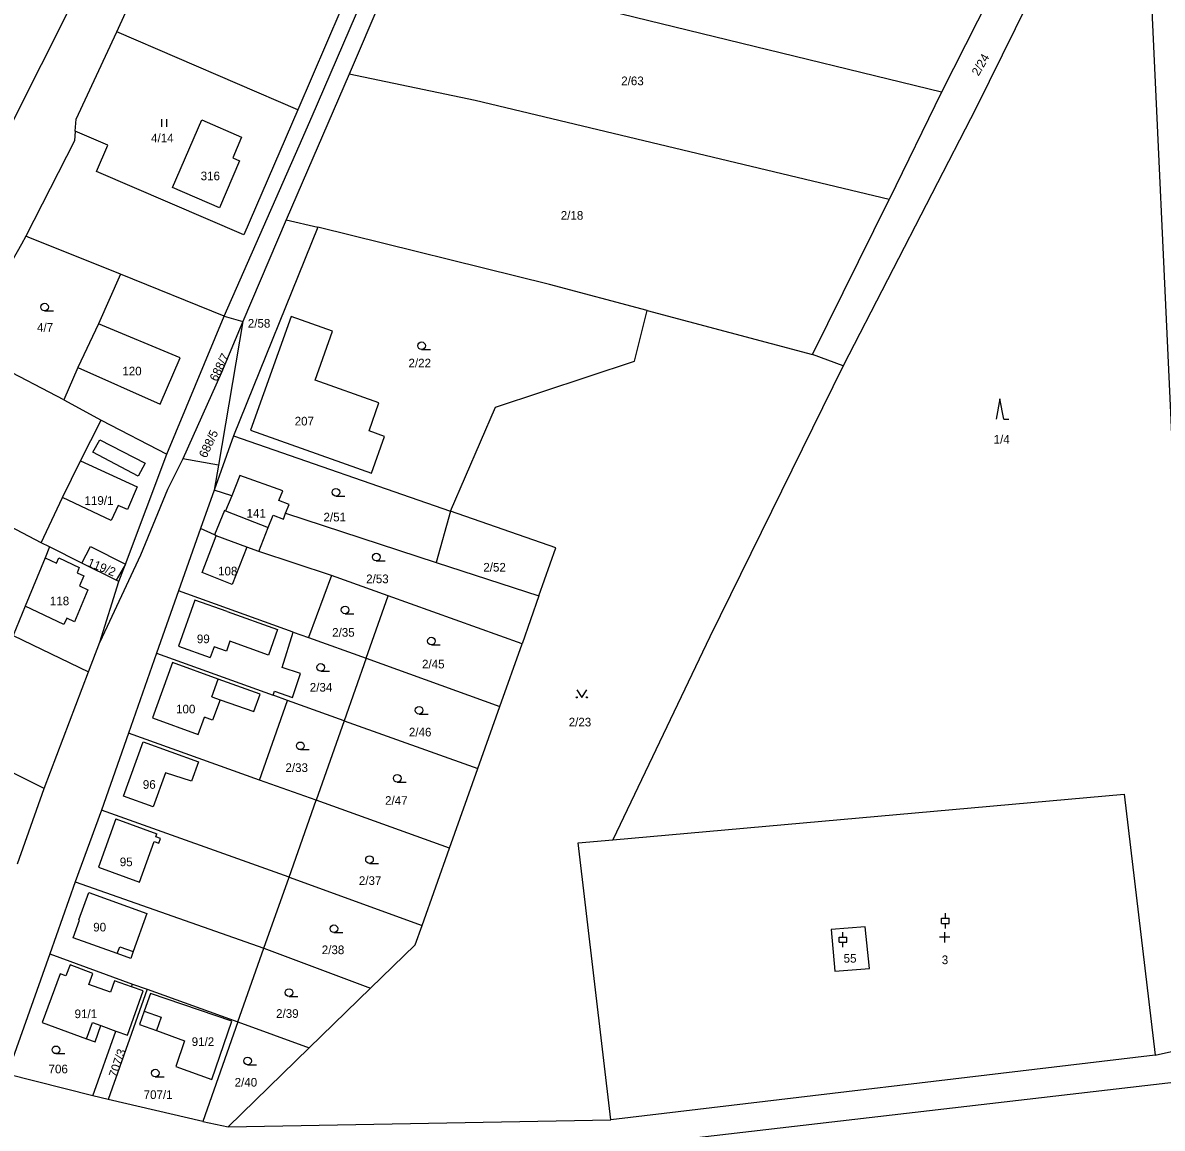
# Model space of a CAD drawing. Extents: x -747333 to -743907, y -1134120 to -1130051.
# Drawn here: x -746109.8 to -745885.9, y -1131640.4 to -1131423.1 of the extents above; entities that cross this region are included whole.
import ezdxf

# ---------------------------------------------------------------- set-up
doc = ezdxf.new("R2010")
doc.units = 0
for name, color, linetype in [('Hranice parcel', 7, 'Continuous'), ('Parcelní čísla', 7, 'Continuous'), ('Vnitřní kresba', 7, 'Continuous'), ('Značky kultur', 7, 'Continuous')]:
    doc.layers.add(name, color=color, linetype=linetype)

msp = doc.modelspace()

# ---------------------------------------------------------------- linework, layer by layer
at = {"layer": 'Hranice parcel'}
for p, q in [((-746091.29, -1131424.93), (-746079.61, -1131398.84)), ((-746036.2, -1131411.06), (-746045.64, -1131433.21)), ((-745919.41, -1131417.32), (-745929.22, -1131436.79)), ((-746055.78, -1131440.25), (-746091.29, -1131424.93)), ((-746045.64, -1131433.21), (-746058.01, -1131461.89)), ((-745929.22, -1131436.79), (-745939.56, -1131457.86)), ((-746099.49, -1131444.41), (-746099.65, -1131446.33)), ((-746099.65, -1131446.33), (-746109.2, -1131465.08)), ((-746070.2, -1131480.79), (-746055.46, -1131447.33)), ((-745954.58, -1131488.31), (-745939.56, -1131457.86)), ((-746051.84, -1131463.28), (-746068.39, -1131504.28)), ((-746058.01, -1131461.89), (-746066.53, -1131481.86)), ((-746058.01, -1131461.89), (-746051.84, -1131463.28)), ((-746070.2, -1131480.79), (-746090.62, -1131472.56)), ((-746081.52, -1131507.94), (-746070.2, -1131480.79)), ((-746070.2, -1131480.79), (-746066.53, -1131481.86)), ((-745987.12, -1131479.66), (-745954.58, -1131488.31)), ((-746066.53, -1131481.86), (-746071.31, -1131510.04)), ((-746101.76, -1131497.26), (-746121.6, -1131486.86)), ((-745948.59, -1131490.54), (-745954.58, -1131488.31)), ((-746101.76, -1131497.26), (-746094.4, -1131501.22)), ((-746094.4, -1131501.22), (-746081.52, -1131507.94)), ((-746068.39, -1131504.28), (-746072.17, -1131514.96)), ((-746068.39, -1131504.28), (-746025.75, -1131519.12)), ((-746089.64, -1131529.49), (-746081.52, -1131507.94)), ((-746071.31, -1131510.04), (-746078.33, -1131508.83)), ((-746071.31, -1131510.04), (-746072.17, -1131514.96)), ((-746106.2, -1131525.3), (-746133.59, -1131510.98)), ((-746072.17, -1131514.96), (-746074.85, -1131522.52)), ((-746058.14, -1131519.53), (-746028.56, -1131529.17)), ((-746025.75, -1131519.12), (-746028.56, -1131529.17)), ((-746074.85, -1131522.52), (-746079.17, -1131534.78)), ((-746104.53, -1131526.13), (-746106.2, -1131525.3)), ((-746098.18, -1131529.3), (-746104.53, -1131526.13)), ((-746049.11, -1131531.76), (-746063.44, -1131527.04)), ((-746090.93, -1131532.92), (-746089.64, -1131529.49)), ((-746028.56, -1131529.17), (-746008.35, -1131535.75)), ((-746094.68, -1131544.83), (-746090.93, -1131532.92)), ((-746049.11, -1131531.76), (-746053.64, -1131543.96)), ((-746038, -1131535.74), (-746049.11, -1131531.76)), ((-746079.17, -1131534.78), (-746083.5, -1131547.04)), ((-746056.65, -1131542.87), (-746079.17, -1131534.78)), ((-746042.33, -1131548.02), (-746038, -1131535.74)), ((-746011.68, -1131545.17), (-746038, -1131535.74)), ((-746008.35, -1131535.75), (-746011.68, -1131545.17)), ((-746111.71, -1131543.57), (-746096.91, -1131550.67)), ((-746056.65, -1131542.87), (-746053.64, -1131543.96)), ((-746053.64, -1131543.96), (-746042.33, -1131548.02)), ((-746096.91, -1131550.67), (-746094.68, -1131544.83)), ((-746016.06, -1131557.46), (-746011.68, -1131545.17)), ((-746083.5, -1131547.04), (-746089.04, -1131562.74)), ((-746083.5, -1131547.04), (-746060.6, -1131555.29)), ((-746042.33, -1131548.02), (-746046.66, -1131560.32)), ((-746042.33, -1131548.02), (-746016.06, -1131557.46)), ((-746105.62, -1131573.59), (-746096.91, -1131550.67)), ((-746057.78, -1131556.31), (-746060.6, -1131555.29)), ((-746063.27, -1131571.95), (-746057.78, -1131556.31)), ((-746046.66, -1131560.32), (-746057.78, -1131556.31)), ((-746020.37, -1131569.7), (-746016.06, -1131557.46)), ((-746046.66, -1131560.32), (-746052.16, -1131575.92)), ((-746046.66, -1131560.32), (-746020.37, -1131569.7)), ((-746089.04, -1131562.74), (-746094.36, -1131577.83)), ((-746063.27, -1131571.95), (-746089.04, -1131562.74)), ((-746025.95, -1131585.34), (-746020.37, -1131569.7)), ((-746052.16, -1131575.92), (-746063.27, -1131571.95)), ((-746110.85, -1131588.4), (-746105.62, -1131573.59)), ((-745993.84, -1131583.67), (-745893.35, -1131574.74)), ((-745893.35, -1131574.74), (-745887.25, -1131625.98)), ((-746057.47, -1131591.02), (-746052.16, -1131575.92)), ((-746025.95, -1131585.34), (-746052.16, -1131575.92)), ((-746094.36, -1131577.83), (-746099.48, -1131591.93)), ((-746057.47, -1131591.02), (-746094.36, -1131577.83)), ((-746031.34, -1131600.5), (-746025.95, -1131585.34)), ((-746062.41, -1131605), (-746057.47, -1131591.02)), ((-746057.47, -1131591.02), (-746031.34, -1131600.5)), ((-746099.48, -1131591.93), (-746104.52, -1131606.12)), ((-746099.48, -1131591.93), (-746062.41, -1131605)), ((-746104.52, -1131606.12), (-746112.88, -1131629.7)), ((-746104.52, -1131606.12), (-746088.22, -1131612.03)), ((-746067.51, -1131619.48), (-746062.41, -1131605)), ((-746062.41, -1131605), (-746041.46, -1131612.82)), ((-746085.34, -1131613.06), (-746093.05, -1131634.69)), ((-746088.41, -1131612.57), (-746088.22, -1131612.03)), ((-746088.22, -1131612.03), (-746085.34, -1131613.06)), ((-746085.34, -1131613.06), (-746067.51, -1131619.48)), ((-746041.46, -1131612.82), (-746053.5, -1131624.53)), ((-746067.51, -1131619.48), (-746074.4, -1131639.02)), ((-746067.51, -1131619.48), (-746053.5, -1131624.53)), ((-746096.04, -1131633.97), (-746091.51, -1131621.25)), ((-746053.5, -1131624.53), (-746069.45, -1131640.11)), ((-745887.25, -1131625.98), (-745877.87, -1131623.88)), ((-745887.25, -1131625.98), (-745994.2, -1131638.7)), ((-746096.04, -1131633.97), (-746112.88, -1131629.7)), ((-746093.05, -1131634.69), (-746096.04, -1131633.97)), ((-746074.4, -1131639.02), (-746093.05, -1131634.69)), ((-746074.4, -1131639.02), (-746069.45, -1131640.11)), ((-746069.45, -1131640.11), (-745994.2, -1131638.7))]:
    msp.add_line(p, q, dxfattribs=at)
for points in [[(-745889.16, -1131372.37), (-745922.43, -1131439.85), (-745948.59, -1131490.54)], [(-745877.87, -1131623.88), (-745879.16, -1131608.6), (-745883.81, -1131508.22), (-745888.44, -1131407.94), (-745889.16, -1131372.37)], [(-746090.75, -1131400.54), (-746121.73, -1131462.2), (-746150.71, -1131520.43), (-746173.33, -1131568.01)], [(-746079.61, -1131398.84), (-746044.46, -1131414), (-746055.78, -1131440.25)], [(-746055.46, -1131447.33), (-746052.93, -1131441.47), (-746038.19, -1131407.28)], [(-745929.22, -1131436.79), (-746018.47, -1131414.97), (-746036.2, -1131411.06)], [(-746099.49, -1131444.41), (-746099.29, -1131442.11), (-746091.29, -1131424.93)], [(-745939.56, -1131457.86), (-746020.87, -1131438.42), (-746045.64, -1131433.21)], [(-746055.78, -1131440.25), (-746066.38, -1131464.83), (-746095.3, -1131452.34), (-746093.06, -1131447.16), (-746099.49, -1131444.41)], [(-746074.64, -1131442.24), (-746066.8, -1131445.62), (-746068.54, -1131449.69), (-746067.19, -1131450.29), (-746071.16, -1131459.52), (-746080.38, -1131455.54), (-746074.64, -1131442.24)], [(-745987.12, -1131479.66), (-746006.29, -1131474.57), (-746051.84, -1131463.28)], [(-746109.2, -1131465.08), (-746110.05, -1131466.67), (-746121.6, -1131486.86)], [(-746090.62, -1131472.56), (-746108.75, -1131465.26), (-746109.2, -1131465.08)], [(-746090.62, -1131472.56), (-746094.92, -1131482.29), (-746098.99, -1131490.89), (-746101.76, -1131497.26)], [(-746052.32, -1131493.39), (-746048.95, -1131483.73), (-746057.08, -1131480.84), (-746065.02, -1131503.16), (-746041.26, -1131511.62), (-746038.7, -1131504.42), (-746041.76, -1131503.33), (-746039.8, -1131497.85), (-746052.32, -1131493.39)], [(-746025.75, -1131519.12), (-746016.9, -1131498.7), (-745989.55, -1131489.64), (-745987.12, -1131479.66)], [(-746066.53, -1131481.86), (-746070.75, -1131491.89), (-746078.33, -1131508.83)], [(-745948.59, -1131490.54), (-745974.76, -1131543.78), (-745993.84, -1131583.67)], [(-746106.2, -1131525.3), (-746102, -1131516.42), (-746098.43, -1131509.2), (-746094.4, -1131501.22)], [(-746078.33, -1131508.83), (-746081.34, -1131514.84), (-746086.66, -1131527.76), (-746094.68, -1131544.83)], [(-746067.15, -1131512.07), (-746068.75, -1131516.07), (-746072.17, -1131514.96)], [(-746058.14, -1131519.53), (-746057.45, -1131517.8), (-746059.47, -1131517), (-746058.72, -1131515.11), (-746067.15, -1131512.07)], [(-746060.61, -1131519.88), (-746058.59, -1131520.68), (-746058.14, -1131519.53)], [(-746008.35, -1131535.75), (-746005.02, -1131526.33), (-746025.75, -1131519.12)], [(-746063.44, -1131527.04), (-746061.57, -1131522.3), (-746060.61, -1131519.88)], [(-746063.44, -1131527.04), (-746065.8, -1131526.18), (-746071.78, -1131523.98), (-746072.11, -1131523.76), (-746074.85, -1131522.52)], [(-746104.53, -1131526.13), (-746105.42, -1131528.29), (-746109.33, -1131537.8), (-746111.71, -1131543.57)], [(-746098.18, -1131529.3), (-746096.51, -1131526.05), (-746089.64, -1131529.49)], [(-746090.93, -1131532.92), (-746091.45, -1131532.66), (-746098.18, -1131529.3)], [(-746060.6, -1131555.29), (-746060.34, -1131554.48), (-746056.82, -1131555.72), (-746055.25, -1131551), (-746058.86, -1131549.83), (-746056.65, -1131542.87)], [(-746105.62, -1131573.59), (-746112.3, -1131570.23), (-746119.76, -1131566.48)], [(-745994.2, -1131638.7), (-746000.67, -1131584.28), (-745993.84, -1131583.67)], [(-746041.46, -1131612.82), (-746032.7, -1131604.32), (-746031.34, -1131600.5)], [(-745950.23, -1131609.5), (-745943.41, -1131608.97), (-745944.27, -1131600.75), (-745950.91, -1131601.29), (-745950.23, -1131609.5)], [(-746088.41, -1131612.57), (-746091.78, -1131611.4), (-746092.55, -1131613.63), (-746096.85, -1131612.12), (-746096.04, -1131609.98), (-746100.51, -1131608.28), (-746101.32, -1131610.42)], [(-746101.32, -1131610.42), (-746102.46, -1131609.99), (-746105.97, -1131619.61)], [(-746091.51, -1131621.25), (-746089.21, -1131622.09), (-746086.16, -1131613.35), (-746088.41, -1131612.57)], [(-746079.75, -1131628.25), (-746072.63, -1131630.79), (-746068.71, -1131619.33), (-746084.68, -1131613.85), (-746085.92, -1131617.33), (-746086.87, -1131619.99), (-746083.54, -1131621.18), (-746078.01, -1131623.15), (-746079.75, -1131628.25)], [(-746105.97, -1131619.61), (-746097.26, -1131622.76), (-746095.6, -1131623.36), (-746094.44, -1131620.17), (-746091.51, -1131621.25)], [(-746011.54, -1131646.14), (-745993.09, -1131644.03), (-745877.4, -1131630.6)]]:
    msp.add_lwpolyline(points, dxfattribs=at)
at = {"layer": 'Vnitřní kresba'}
for p, q in [((-746078.88, -1131488.97), (-746094.92, -1131482.29)), ((-746082.79, -1131498.11), (-746078.88, -1131488.97)), ((-746098.99, -1131490.89), (-746082.79, -1131498.11)), ((-746098.43, -1131509.2), (-746087.32, -1131514.31)), ((-746087.32, -1131514.31), (-746089.24, -1131518.76)), ((-746092.41, -1131520.95), (-746102, -1131516.42)), ((-746068.75, -1131516.07), (-746069.95, -1131519.06)), ((-746091.06, -1131518), (-746092.41, -1131520.95)), ((-746089.24, -1131518.76), (-746091.06, -1131518)), ((-746070.19, -1131518.96), (-746072.11, -1131523.76)), ((-746069.95, -1131519.06), (-746070.19, -1131518.96)), ((-746069.95, -1131519.06), (-746061.57, -1131522.3)), ((-746074.58, -1131531.19), (-746071.78, -1131523.98)), ((-746065.8, -1131526.18), (-746068.67, -1131533.49)), ((-746105.42, -1131528.29), (-746103.17, -1131529.3)), ((-746103.17, -1131529.3), (-746102.7, -1131528.25)), ((-746102.7, -1131528.25), (-746098.72, -1131530.19)), ((-746098.72, -1131530.19), (-746099.14, -1131531.24)), ((-746089.64, -1131529.49), (-746091.45, -1131532.66)), ((-746099.14, -1131531.24), (-746097.83, -1131531.81)), ((-746097.83, -1131531.81), (-746098.67, -1131533.75)), ((-746068.67, -1131533.49), (-746074.58, -1131531.19)), ((-746096.99, -1131534.59), (-746099.66, -1131540.82)), ((-746098.67, -1131533.75), (-746096.99, -1131534.59)), ((-746075.98, -1131536.58), (-746079.22, -1131545.62)), ((-746069.66, -1131538.85), (-746075.98, -1131536.58)), ((-746101.76, -1131541.4), (-746109.33, -1131537.8)), ((-746069.66, -1131538.85), (-746059.72, -1131542.38)), ((-746101.18, -1131540.14), (-746101.76, -1131541.4)), ((-746099.66, -1131540.82), (-746101.18, -1131540.14)), ((-746059.72, -1131542.38), (-746061.54, -1131547.37)), ((-746079.22, -1131545.62), (-746072.97, -1131547.89)), ((-746072.19, -1131545.75), (-746072.97, -1131547.89)), ((-746069.8, -1131546.61), (-746072.19, -1131545.75)), ((-746069.09, -1131544.64), (-746069.8, -1131546.61)), ((-746061.54, -1131547.37), (-746069.09, -1131544.64)), ((-746080.4, -1131548.87), (-746084.32, -1131559.72)), ((-746071.42, -1131552.11), (-746080.4, -1131548.87)), ((-746072.67, -1131555.57), (-746071.42, -1131552.11)), ((-746063.13, -1131555.05), (-746071.42, -1131552.11)), ((-746064.37, -1131558.5), (-746063.13, -1131555.05)), ((-746072.67, -1131555.57), (-746071.03, -1131556.16)), ((-746071.03, -1131556.16), (-746072.49, -1131560.18)), ((-746071.03, -1131556.16), (-746064.37, -1131558.5)), ((-746084.32, -1131559.72), (-746075.34, -1131562.96)), ((-746075.34, -1131562.96), (-746074.12, -1131559.59)), ((-746072.49, -1131560.18), (-746074.12, -1131559.59)), ((-746090, -1131575.09), (-746086.12, -1131564.44)), ((-746086.12, -1131564.44), (-746075.27, -1131568.39)), ((-746075.27, -1131568.39), (-746076.66, -1131572.19)), ((-746081.74, -1131570.54), (-746084.17, -1131577.21)), ((-746076.66, -1131572.19), (-746081.74, -1131570.54)), ((-746084.17, -1131577.21), (-746090, -1131575.09)), ((-746091.51, -1131579.58), (-746094.94, -1131589.09)), ((-746091.51, -1131579.58), (-746083.45, -1131582.49)), ((-746086.88, -1131592), (-746084, -1131584.03)), ((-746084, -1131584.03), (-746083.07, -1131584.36)), ((-746083.67, -1131583.1), (-746083.45, -1131582.49)), ((-746082.74, -1131583.43), (-746083.67, -1131583.1)), ((-746083.07, -1131584.36), (-746082.74, -1131583.43)), ((-746094.94, -1131589.09), (-746086.88, -1131592)), ((-746098.78, -1131599.41), (-746096.83, -1131594.01)), ((-746096.83, -1131594.01), (-746085.44, -1131598.13)), ((-746099.92, -1131602.97), (-746098.64, -1131599.46)), ((-746098.64, -1131599.46), (-746098.78, -1131599.41)), ((-746085.44, -1131598.13), (-746088.1, -1131605.65)), ((-746091.24, -1131606.05), (-746099.92, -1131602.97)), ((-746091.24, -1131606.05), (-746090.75, -1131604.71)), ((-746088.58, -1131607), (-746091.24, -1131606.05)), ((-746090.75, -1131604.71), (-746088.1, -1131605.65)), ((-746088.1, -1131605.65), (-746088.58, -1131607)), ((-746085.92, -1131617.33), (-746082.59, -1131618.51)), ((-746082.59, -1131618.51), (-746083.54, -1131621.18))]:
    msp.add_line(p, q, dxfattribs=at)
for points in [[(-746094.67, -1131505.08), (-746085.75, -1131509.67), (-746087.16, -1131512.22), (-746096.03, -1131507.54), (-746094.67, -1131505.08)], [(-746097.26, -1131622.76), (-746096.1, -1131619.56), (-746094.44, -1131620.17)]]:
    msp.add_lwpolyline(points, dxfattribs=at)
at = {"layer": 'Značky kultur'}
for p, q in [((-746082.501, -1131443.56), (-746082.501, -1131442.06)), ((-746081.5, -1131443.56), (-746081.5, -1131442.06)), ((-746105.513, -1131479.75), (-746103.763, -1131479.75)), ((-746031.423, -1131487.35), (-746029.673, -1131487.35)), ((-745917.77, -1131497.05), (-745918.52, -1131501.05)), ((-745917.02, -1131501.05), (-745917.77, -1131497.05)), ((-745917.02, -1131501.05), (-745916.024, -1131501.05)), ((-746048.263, -1131516.13), (-746046.513, -1131516.13)), ((-746040.323, -1131528.88), (-746038.573, -1131528.88)), ((-746046.463, -1131539.25), (-746044.713, -1131539.25)), ((-746029.493, -1131545.39), (-746027.743, -1131545.39)), ((-746051.243, -1131550.57), (-746049.493, -1131550.57)), ((-746031.913, -1131558.98), (-746030.163, -1131558.98)), ((-746055.253, -1131565.97), (-746053.503, -1131565.97)), ((-746036.213, -1131572.35), (-746034.463, -1131572.35)), ((-746041.663, -1131588.32), (-746039.913, -1131588.32)), ((-745929.231, -1131599.101), (-745927.729, -1131599.101)), ((-745929.231, -1131600.102), (-745929.231, -1131599.101)), ((-745929.231, -1131600.102), (-745927.729, -1131600.102)), ((-745928.48, -1131599.101), (-745928.48, -1131598.1)), ((-745928.48, -1131601.1), (-745928.48, -1131600.102)), ((-745927.729, -1131600.102), (-745927.729, -1131599.101)), ((-746048.653, -1131601.92), (-746046.903, -1131601.92)), ((-745948.63, -1131602.801), (-745948.63, -1131601.8)), ((-745928.62, -1131603.83), (-745928.62, -1131601.83)), ((-745949.381, -1131602.801), (-745947.879, -1131602.801)), ((-745949.381, -1131603.802), (-745949.381, -1131602.801)), ((-745949.381, -1131603.802), (-745947.879, -1131603.802)), ((-745948.63, -1131604.8), (-745948.63, -1131603.802)), ((-745947.879, -1131603.802), (-745947.879, -1131602.801)), ((-745927.619, -1131602.831), (-745929.621, -1131602.831)), ((-746057.483, -1131614.44), (-746055.733, -1131614.44)), ((-746103.293, -1131625.7), (-746101.543, -1131625.7)), ((-746065.623, -1131627.88), (-746063.873, -1131627.88)), ((-746083.783, -1131630.27), (-746082.033, -1131630.27))]:
    msp.add_line(p, q, dxfattribs=at)
msp.add_lwpolyline([(-746000.94, -1131554.189), (-745999.94, -1131555.69), (-745998.94, -1131554.189)], dxfattribs=at)
for centre, radius in [((-746105.513, -1131479), 0.75), ((-746031.423, -1131486.6), 0.75), ((-746048.263, -1131515.38), 0.75), ((-746040.323, -1131528.13), 0.75), ((-746046.463, -1131538.5), 0.75), ((-746029.493, -1131544.64), 0.75), ((-746051.243, -1131549.82), 0.75), ((-746031.913, -1131558.23), 0.75), ((-746000.94, -1131555.689), 0.1), ((-745998.94, -1131555.689), 0.1), ((-746055.253, -1131565.22), 0.75), ((-746036.213, -1131571.6), 0.75), ((-746041.663, -1131587.57), 0.75), ((-746048.653, -1131601.17), 0.75), ((-746057.483, -1131613.69), 0.75), ((-746103.293, -1131624.95), 0.75), ((-746065.623, -1131627.13), 0.75), ((-746083.783, -1131629.52), 0.75)]:
    msp.add_circle(centre, radius, dxfattribs=at)

# ---------------------------------------------------------------- texts
at = {"layer": 'Parcelní čísla'}
for s, rotation, p in [('2/24', 60, (-745921.963, -1131433.715)), ('688/7', 64, (-746071.661, -1131493.745)), ('688/5', 65, (-746073.739, -1131508.799)), ('119/2', 338, (-746097.249, -1131529.839)), ('707/3', 71, (-746091.359, -1131630.519))]:
    msp.add_text(s, height=1.7, rotation=rotation, dxfattribs=at).set_placement(p)
for s, p in [('2/63', (-745992.19, -1131435.41)), ('4/14', (-746084.591, -1131446.64)), ('316', (-746074.844, -1131454.09)), ('2/18', (-746004.07, -1131461.84)), ('2/58', (-746065.58, -1131483.05)), ('4/7', (-746107, -1131483.85)), ('2/22', (-746034, -1131490.85)), ('120', (-746090.24, -1131492.43)), ('207', (-746056.37, -1131502.27)), ('1/4', (-745919, -1131505.85)), ('119/1', (-746097.673, -1131517.87)), ('141', (-746065.82, -1131520.36)), ('2/51', (-746050.7, -1131521.12)), ('108', (-746071.42, -1131531.73)), ('2/52', (-746019.29, -1131530.98)), ('2/53', (-746042.32, -1131533.26)), ('118', (-746104.48, -1131537.59)), ('99', (-746075.59, -1131545.05)), ('2/35', (-746049, -1131543.78)), ('2/45', (-746031.34, -1131550)), ('2/34', (-746053.4, -1131554.57)), ('100', (-746079.68, -1131558.84)), ('2/23', (-746002.51, -1131561.4)), ('2/46', (-746033.92, -1131563.37)), ('2/33', (-746058.18, -1131570.36)), ('96', (-746086.21, -1131573.66)), ('2/47', (-746038.6, -1131576.81)), ('95', (-746090.74, -1131588.87)), ('2/37', (-746043.75, -1131592.55)), ('90', (-746095.96, -1131601.69)), ('2/38', (-746051.04, -1131606.15)), ('55', (-745948.48, -1131607.82)), ('3', (-745929.19, -1131608.11)), ('91/1', (-746099.63, -1131618.72)), ('2/39', (-746060.02, -1131618.67)), ('91/2', (-746076.61, -1131624.19)), ('706', (-746104.74, -1131629.56)), ('2/40', (-746068.17, -1131632.18)), ('707/1', (-746086.053, -1131634.61))]:
    msp.add_text(s, height=1.7, dxfattribs=at).set_placement(p)

doc.saveas('drawing.dxf')
